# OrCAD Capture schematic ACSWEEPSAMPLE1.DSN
size A
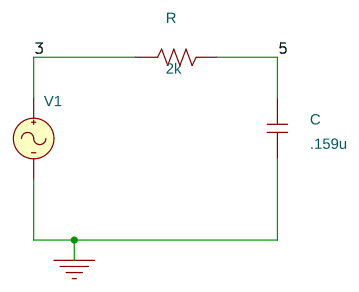
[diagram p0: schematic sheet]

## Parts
C  .159u  [RAD/CK05]
R  2k  [AX/RC05]
V1  VAC

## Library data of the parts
C = C
R = R
V1 = VAC

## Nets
0: C.1 V1.2(-)
3: R.1 V1.1(+)
5: C.2 R.2
